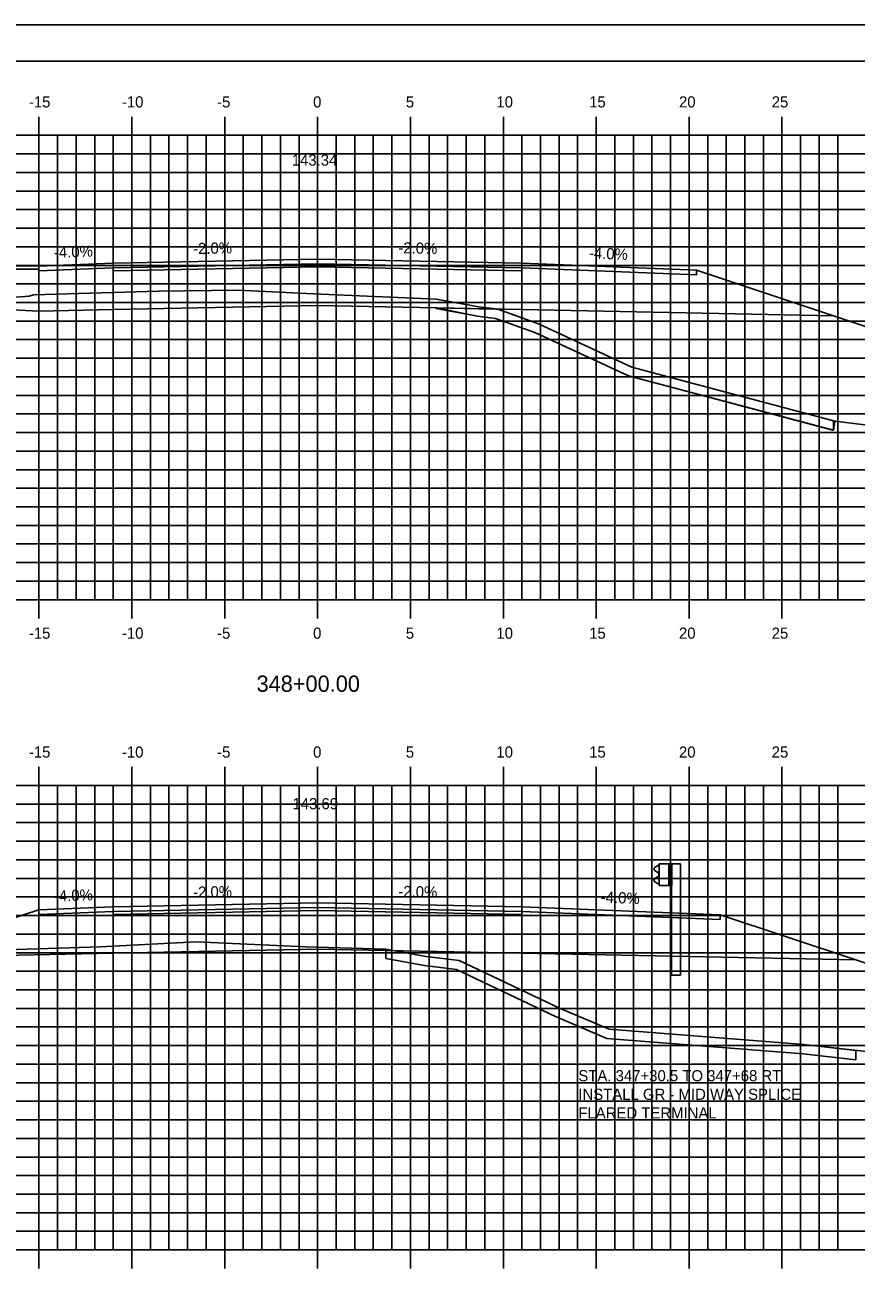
# Model space of a CAD drawing. Extents: x 1144085 to 1144255, y 608981 to 609091.
# Drawn here: x 1144152.6 to 1144197.3, y 609024.1 to 609091.3 of the extents above; entities that cross this region are included whole.
import ezdxf

# ---------------------------------------------------------------- set-up
doc = ezdxf.new("R2010")
doc.units = 0
for name, color, linetype in [('ANNOTATION', 7, 'Continuous'), ('BORDER', 7, 'Continuous'), ('D_Guardrail_Beam_Rt', 7, 'Continuous'), ('D_Guardrail_ConcBarrier', 7, 'Continuous'), ('D_Roadway_Centerline', 7, 'Continuous'), ('D_Roadway_Centerline_Text', 7, 'Continuous'), ('D_Roadway_Edge_Shoulder', 7, 'Continuous'), ('D_Roadway_Edge_TW', 7, 'Continuous'), ('D_Roadway_Pavement', 7, 'Continuous'), ('D_Roadway_SlopeLines', 7, 'Continuous'), ('D_Roadway_SubGrade', 7, 'Continuous'), ('H_V ANNOTATION', 7, 'Continuous'), ('MAJOR', 7, 'Continuous'), ('MINOR', 7, 'Continuous'), ('PLOT BOUNDARY', 7, 'Continuous'), ('S_Roadway_Centerline', 7, 'Continuous'), ('SHADING', 7, 'Continuous')]:
    doc.layers.add(name, color=color, linetype=linetype)

msp = doc.modelspace()

# ---------------------------------------------------------------- linework, layer by layer
for points in [[(1144123.068, 609078.385), (1144153.349, 609078.292), (1144157.349, 609078.452), (1144168.349, 609078.672), (1144179.349, 609078.452), (1144188.751, 609078.076), (1144196.129, 609075.617), (1144199.129, 609074.617), (1144217.63, 609068.45)], [(1144136.907, 609038.164), (1144142.311, 609040.063), (1144145.395, 609041.063), (1144153.348, 609043.642), (1144153.349, 609043.642), (1144157.349, 609043.802), (1144168.349, 609044.022), (1144179.349, 609043.802), (1144190.025, 609043.375), (1144197.322, 609040.943), (1144200.322, 609039.943), (1144215.637, 609034.838)]]:
    msp.add_lwpolyline(points)
at = {"layer": 'BORDER'}
msp.add_lwpolyline([(1144093.349, 608984.335), (1144253.349, 608984.335), (1144253.349, 609089.335), (1144093.349, 609089.335)], close=True, dxfattribs=at)
at = {"layer": 'D_Guardrail_Beam_Rt'}
for p, q in [((1144186.639, 609046.015), (1144186.495, 609045.915)), ((1144186.495, 609045.772), (1144186.691, 609045.636)), ((1144186.729, 609046.036), (1144186.655, 609046.022)), ((1144186.691, 609045.437), (1144186.495, 609045.301)), ((1144186.495, 609045.158), (1144186.639, 609045.058)), ((1144186.655, 609045.051), (1144186.729, 609045.036)), ((1144186.724, 609045.572), (1144186.724, 609045.501))]:
    msp.add_line(p, q, dxfattribs=at)
for centre, major_axis, start_param, end_param in [((1144186.546, 609045.844), (-0.0877, 0), 5.323254, 7.243116), ((1144186.663, 609045.981), (-0.0417, 0), 4.907132, 5.323254), ((1144186.645, 609045.572), (0.0789, 0), 0, 0.959931), ((1144186.546, 609045.229), (-0.0877, 0), 5.323254, 7.243116), ((1144186.663, 609045.092), (-0.0417, 0), 0.959931, 1.376053), ((1144186.645, 609045.501), (0.0789, 0), 5.323254, 6.283185)]:
    msp.add_ellipse(centre, major_axis=major_axis, ratio=0.995501, start_param=start_param, end_param=end_param, dxfattribs=at)
at = {"layer": 'D_Guardrail_ConcBarrier'}
for p, q in [((1144186.729, 609046.12), (1144187.416, 609046.12)), ((1144186.729, 609044.953), (1144186.729, 609046.12)), ((1144187.25, 609046.12), (1144187.25, 609044.953)), ((1144187.354, 609046.12), (1144187.354, 609044.953)), ((1144187.416, 609046.12), (1144187.887, 609046.12)), ((1144187.416, 609046.12), (1144187.416, 609044.953)), ((1144187.887, 609046.12), (1144187.887, 609040.12)), ((1144187.416, 609044.953), (1144186.729, 609044.953)), ((1144187.396, 609040.12), (1144187.396, 609044.953)), ((1144187.396, 609040.12), (1144187.887, 609040.12))]:
    msp.add_line(p, q, dxfattribs=at)
at = {"layer": 'D_Roadway_Edge_Shoulder'}
for points in [[(1144153.349, 609078.292), (1144150.349, 609078.301), (1144150.349, 609078.135), (1144153.349, 609078.126)], [(1144157.349, 609078.452), (1144153.349, 609078.292), (1144153.349, 609078.042), (1144157.349, 609078.202)], [(1144179.349, 609078.452), (1144188.751, 609078.076), (1144188.751, 609077.826), (1144179.349, 609078.202)], [(1144157.349, 609043.802), (1144153.349, 609043.642), (1144153.349, 609043.392), (1144157.349, 609043.552)], [(1144179.349, 609043.802), (1144190.025, 609043.375), (1144190.025, 609043.125), (1144179.349, 609043.552)]]:
    msp.add_lwpolyline(points, close=True, dxfattribs=at)
at = {"layer": 'D_Roadway_Edge_TW'}
for points in [[(1144157.349, 609078.202), (1144157.349, 609078.452), (1144168.349, 609078.672), (1144179.349, 609078.452), (1144179.349, 609078.202), (1144168.349, 609078.422)], [(1144157.349, 609043.552), (1144157.349, 609043.802), (1144168.349, 609044.022), (1144179.349, 609043.802), (1144179.349, 609043.552), (1144168.349, 609043.772)]]:
    msp.add_lwpolyline(points, close=True, dxfattribs=at)
at = {"layer": 'D_Roadway_Pavement'}
for points in [[(1144157.349, 609078.036), (1144157.349, 609078.202), (1144168.349, 609078.422), (1144179.349, 609078.202), (1144179.349, 609078.036), (1144168.349, 609078.256)], [(1144157.349, 609043.386), (1144157.349, 609043.552), (1144168.349, 609043.772), (1144179.349, 609043.552), (1144179.349, 609043.386), (1144168.349, 609043.606)]]:
    msp.add_lwpolyline(points, close=True, dxfattribs=at)
at = {"layer": 'D_Roadway_SlopeLines'}
for p, q in [((1144174.737, 609076.044), (1144174.737, 609076.008)), ((1144196.129, 609069.967), (1144196.129, 609069.455)), ((1144172.025, 609041.53), (1144172.025, 609041.03)), ((1144197.322, 609036.074), (1144197.322, 609035.573))]:
    msp.add_line(p, q, dxfattribs=at)
for points in [[(1144174.737, 609076.008), (1144176.951, 609075.599), (1144177.932, 609075.479), (1144180.051, 609074.727), (1144185.091, 609072.384), (1144196.092, 609069.46), (1144196.129, 609069.455)], [(1144196.129, 609075.617), (1144199.129, 609074.617)], [(1144172.025, 609041.024), (1144174.11, 609040.638), (1144175.834, 609040.428), (1144181.164, 609037.901), (1144183.926, 609036.722), (1144194.481, 609035.887), (1144197.322, 609035.573)], [(1144197.322, 609040.943), (1144200.322, 609039.943)]]:
    msp.add_lwpolyline(points, dxfattribs=at)
at = {"layer": 'D_Roadway_SubGrade'}
for points in [[(1144123.068, 609077.385), (1144153.349, 609075.872), (1144157.349, 609075.952), (1144157.349, 609078.036), (1144157.349, 609078.202), (1144153.349, 609078.042), (1144153.349, 609078.292), (1144123.068, 609078.385)], [(1144157.349, 609075.952), (1144157.349, 609078.036), (1144168.349, 609078.256), (1144179.349, 609078.036), (1144179.349, 609075.952), (1144168.349, 609076.172)], [(1144179.349, 609078.036), (1144179.349, 609078.202), (1144188.751, 609077.826), (1144188.751, 609078.076), (1144188.751, 609078.076), (1144196.129, 609075.617), (1144179.349, 609075.952)], [(1144157.349, 609043.386), (1144157.349, 609043.552), (1144153.349, 609043.392), (1144153.349, 609043.642), (1144153.348, 609043.642), (1144145.395, 609041.063), (1144157.349, 609041.302)], [(1144157.349, 609041.302), (1144157.349, 609043.386), (1144168.349, 609043.606), (1144179.349, 609043.386), (1144179.349, 609041.302), (1144168.349, 609041.522)], [(1144179.349, 609043.386), (1144179.349, 609043.552), (1144190.025, 609043.125), (1144190.025, 609043.375), (1144190.025, 609043.375), (1144197.322, 609040.943), (1144179.349, 609041.302)]]:
    msp.add_lwpolyline(points, close=True, dxfattribs=at)
at = {"layer": 'MAJOR'}
for p, q in [((1144153.349, 609086.337), (1144153.349, 609085.335)), ((1144158.349, 609086.337), (1144158.349, 609085.335)), ((1144163.349, 609086.337), (1144163.349, 609085.335)), ((1144168.349, 609086.337), (1144168.349, 609085.335)), ((1144173.349, 609086.337), (1144173.349, 609085.335)), ((1144178.349, 609086.337), (1144178.349, 609085.335)), ((1144183.349, 609086.337), (1144183.349, 609085.335)), ((1144188.349, 609086.337), (1144188.349, 609085.335)), ((1144193.349, 609086.337), (1144193.349, 609085.335)), ((1144098.349, 609085.335), (1144238.349, 609085.335)), ((1144098.349, 609085.335), (1144238.349, 609085.335)), ((1144153.349, 609060.335), (1144153.349, 609085.335)), ((1144158.349, 609060.335), (1144158.349, 609085.335)), ((1144163.349, 609060.335), (1144163.349, 609085.335)), ((1144168.349, 609060.335), (1144168.349, 609085.335)), ((1144173.349, 609060.335), (1144173.349, 609085.335)), ((1144178.349, 609060.335), (1144178.349, 609085.335)), ((1144183.349, 609060.335), (1144183.349, 609085.335)), ((1144188.349, 609060.335), (1144188.349, 609085.335)), ((1144193.349, 609060.335), (1144193.349, 609085.335)), ((1144098.349, 609080.335), (1144238.349, 609080.335)), ((1144098.349, 609075.335), (1144238.349, 609075.335)), ((1144098.349, 609070.335), (1144238.349, 609070.335)), ((1144098.349, 609065.335), (1144238.349, 609065.335)), ((1144098.349, 609060.335), (1144238.349, 609060.335)), ((1144098.349, 609060.335), (1144238.349, 609060.335)), ((1144153.349, 609059.333), (1144153.349, 609060.335)), ((1144158.349, 609059.333), (1144158.349, 609060.335)), ((1144163.349, 609059.333), (1144163.349, 609060.335)), ((1144168.349, 609059.333), (1144168.349, 609060.335)), ((1144173.349, 609059.333), (1144173.349, 609060.335)), ((1144178.349, 609059.333), (1144178.349, 609060.335)), ((1144183.349, 609059.333), (1144183.349, 609060.335)), ((1144188.349, 609059.333), (1144188.349, 609060.335)), ((1144193.349, 609059.333), (1144193.349, 609060.335)), ((1144153.349, 609051.337), (1144153.349, 609050.335)), ((1144158.349, 609051.337), (1144158.349, 609050.335)), ((1144163.349, 609051.337), (1144163.349, 609050.335)), ((1144168.349, 609051.337), (1144168.349, 609050.335)), ((1144173.349, 609051.337), (1144173.349, 609050.335)), ((1144178.349, 609051.337), (1144178.349, 609050.335)), ((1144183.349, 609051.337), (1144183.349, 609050.335)), ((1144188.349, 609051.337), (1144188.349, 609050.335)), ((1144193.349, 609051.337), (1144193.349, 609050.335)), ((1144098.349, 609050.335), (1144238.349, 609050.335)), ((1144098.349, 609050.335), (1144238.349, 609050.335)), ((1144153.349, 609025.335), (1144153.349, 609050.335)), ((1144158.349, 609025.335), (1144158.349, 609050.335)), ((1144163.349, 609025.335), (1144163.349, 609050.335)), ((1144168.349, 609025.335), (1144168.349, 609050.335)), ((1144173.349, 609025.335), (1144173.349, 609050.335)), ((1144178.349, 609025.335), (1144178.349, 609050.335)), ((1144183.349, 609025.335), (1144183.349, 609050.335)), ((1144188.349, 609025.335), (1144188.349, 609050.335)), ((1144193.349, 609025.335), (1144193.349, 609050.335)), ((1144098.349, 609045.335), (1144238.349, 609045.335)), ((1144098.349, 609040.335), (1144238.349, 609040.335)), ((1144098.349, 609035.335), (1144238.349, 609035.335)), ((1144098.349, 609030.335), (1144238.349, 609030.335)), ((1144098.349, 609025.335), (1144238.349, 609025.335)), ((1144098.349, 609025.335), (1144238.349, 609025.335)), ((1144153.349, 609024.333), (1144153.349, 609025.335)), ((1144158.349, 609024.333), (1144158.349, 609025.335)), ((1144163.349, 609024.333), (1144163.349, 609025.335)), ((1144168.349, 609024.333), (1144168.349, 609025.335)), ((1144173.349, 609024.333), (1144173.349, 609025.335)), ((1144178.349, 609024.333), (1144178.349, 609025.335)), ((1144183.349, 609024.333), (1144183.349, 609025.335)), ((1144188.349, 609024.333), (1144188.349, 609025.335)), ((1144193.349, 609024.333), (1144193.349, 609025.335))]:
    msp.add_line(p, q, dxfattribs=at)
at = {"layer": 'MINOR'}
for p, q in [((1144154.349, 609060.335), (1144154.349, 609085.335)), ((1144155.349, 609060.335), (1144155.349, 609085.335)), ((1144156.349, 609060.335), (1144156.349, 609085.335)), ((1144157.349, 609060.335), (1144157.349, 609085.335)), ((1144159.349, 609060.335), (1144159.349, 609085.335)), ((1144160.349, 609060.335), (1144160.349, 609085.335)), ((1144161.349, 609060.335), (1144161.349, 609085.335)), ((1144162.349, 609060.335), (1144162.349, 609085.335)), ((1144164.349, 609060.335), (1144164.349, 609085.335)), ((1144165.349, 609060.335), (1144165.349, 609085.335)), ((1144166.349, 609060.335), (1144166.349, 609085.335)), ((1144167.349, 609060.335), (1144167.349, 609085.335)), ((1144169.349, 609060.335), (1144169.349, 609085.335)), ((1144170.349, 609060.335), (1144170.349, 609085.335)), ((1144171.349, 609060.335), (1144171.349, 609085.335)), ((1144172.349, 609060.335), (1144172.349, 609085.335)), ((1144174.349, 609060.335), (1144174.349, 609085.335)), ((1144175.349, 609060.335), (1144175.349, 609085.335)), ((1144176.349, 609060.335), (1144176.349, 609085.335)), ((1144177.349, 609060.335), (1144177.349, 609085.335)), ((1144179.349, 609060.335), (1144179.349, 609085.335)), ((1144180.349, 609060.335), (1144180.349, 609085.335)), ((1144181.349, 609060.335), (1144181.349, 609085.335)), ((1144182.349, 609060.335), (1144182.349, 609085.335)), ((1144184.349, 609060.335), (1144184.349, 609085.335)), ((1144185.349, 609060.335), (1144185.349, 609085.335)), ((1144186.349, 609060.335), (1144186.349, 609085.335)), ((1144187.349, 609060.335), (1144187.349, 609085.335)), ((1144189.349, 609060.335), (1144189.349, 609085.335)), ((1144190.349, 609060.335), (1144190.349, 609085.335)), ((1144191.349, 609060.335), (1144191.349, 609085.335)), ((1144192.349, 609060.335), (1144192.349, 609085.335)), ((1144194.349, 609060.335), (1144194.349, 609085.335)), ((1144195.349, 609060.335), (1144195.349, 609085.335)), ((1144196.349, 609060.335), (1144196.349, 609085.335)), ((1144098.349, 609084.335), (1144238.349, 609084.335)), ((1144098.349, 609083.335), (1144238.349, 609083.335)), ((1144098.349, 609082.335), (1144238.349, 609082.335)), ((1144098.349, 609081.335), (1144238.349, 609081.335)), ((1144098.349, 609079.335), (1144238.349, 609079.335)), ((1144098.349, 609078.335), (1144238.349, 609078.335)), ((1144098.349, 609077.335), (1144238.349, 609077.335)), ((1144098.349, 609076.335), (1144238.349, 609076.335)), ((1144098.349, 609074.335), (1144238.349, 609074.335)), ((1144098.349, 609073.335), (1144238.349, 609073.335)), ((1144098.349, 609072.335), (1144238.349, 609072.335)), ((1144098.349, 609071.335), (1144238.349, 609071.335)), ((1144098.349, 609069.335), (1144238.349, 609069.335)), ((1144098.349, 609068.335), (1144238.349, 609068.335)), ((1144098.349, 609067.335), (1144238.349, 609067.335)), ((1144098.349, 609066.335), (1144238.349, 609066.335)), ((1144098.349, 609064.335), (1144238.349, 609064.335)), ((1144098.349, 609063.335), (1144238.349, 609063.335)), ((1144098.349, 609062.335), (1144238.349, 609062.335)), ((1144098.349, 609061.335), (1144238.349, 609061.335)), ((1144154.349, 609025.335), (1144154.349, 609050.335)), ((1144155.349, 609025.335), (1144155.349, 609050.335)), ((1144156.349, 609025.335), (1144156.349, 609050.335)), ((1144157.349, 609025.335), (1144157.349, 609050.335)), ((1144159.349, 609025.335), (1144159.349, 609050.335)), ((1144160.349, 609025.335), (1144160.349, 609050.335)), ((1144161.349, 609025.335), (1144161.349, 609050.335)), ((1144162.349, 609025.335), (1144162.349, 609050.335)), ((1144164.349, 609025.335), (1144164.349, 609050.335)), ((1144165.349, 609025.335), (1144165.349, 609050.335)), ((1144166.349, 609025.335), (1144166.349, 609050.335)), ((1144167.349, 609025.335), (1144167.349, 609050.335)), ((1144169.349, 609025.335), (1144169.349, 609050.335)), ((1144170.349, 609025.335), (1144170.349, 609050.335)), ((1144171.349, 609025.335), (1144171.349, 609050.335)), ((1144172.349, 609025.335), (1144172.349, 609050.335)), ((1144174.349, 609025.335), (1144174.349, 609050.335)), ((1144175.349, 609025.335), (1144175.349, 609050.335)), ((1144176.349, 609025.335), (1144176.349, 609050.335)), ((1144177.349, 609025.335), (1144177.349, 609050.335)), ((1144179.349, 609025.335), (1144179.349, 609050.335)), ((1144180.349, 609025.335), (1144180.349, 609050.335)), ((1144181.349, 609025.335), (1144181.349, 609050.335)), ((1144182.349, 609025.335), (1144182.349, 609050.335)), ((1144184.349, 609025.335), (1144184.349, 609050.335)), ((1144185.349, 609025.335), (1144185.349, 609050.335)), ((1144186.349, 609025.335), (1144186.349, 609050.335)), ((1144187.349, 609025.335), (1144187.349, 609050.335)), ((1144189.349, 609025.335), (1144189.349, 609050.335)), ((1144190.349, 609025.335), (1144190.349, 609050.335)), ((1144191.349, 609025.335), (1144191.349, 609050.335)), ((1144192.349, 609025.335), (1144192.349, 609050.335)), ((1144194.349, 609025.335), (1144194.349, 609050.335)), ((1144195.349, 609025.335), (1144195.349, 609050.335)), ((1144196.349, 609025.335), (1144196.349, 609050.335)), ((1144098.349, 609049.335), (1144238.349, 609049.335)), ((1144098.349, 609048.335), (1144238.349, 609048.335)), ((1144098.349, 609047.335), (1144238.349, 609047.335)), ((1144098.349, 609046.335), (1144238.349, 609046.335)), ((1144098.349, 609044.335), (1144238.349, 609044.335)), ((1144098.349, 609043.335), (1144238.349, 609043.335)), ((1144098.349, 609042.335), (1144238.349, 609042.335)), ((1144098.349, 609041.335), (1144238.349, 609041.335)), ((1144098.349, 609039.335), (1144238.349, 609039.335)), ((1144098.349, 609038.335), (1144238.349, 609038.335)), ((1144098.349, 609037.335), (1144238.349, 609037.335)), ((1144098.349, 609036.335), (1144238.349, 609036.335)), ((1144098.349, 609034.335), (1144238.349, 609034.335)), ((1144098.349, 609033.335), (1144238.349, 609033.335)), ((1144098.349, 609032.335), (1144238.349, 609032.335)), ((1144098.349, 609031.335), (1144238.349, 609031.335)), ((1144098.349, 609029.335), (1144238.349, 609029.335)), ((1144098.349, 609028.335), (1144238.349, 609028.335)), ((1144098.349, 609027.335), (1144238.349, 609027.335)), ((1144098.349, 609026.335), (1144238.349, 609026.335))]:
    msp.add_line(p, q, dxfattribs=at)
at = {"layer": 'PLOT BOUNDARY'}
msp.add_lwpolyline([(1144085.256, 608981.276), (1144255.256, 608981.276), (1144255.256, 609091.276), (1144085.256, 609091.276)], close=True, dxfattribs=at)
at = {"layer": 'S_Roadway_Centerline'}
for points in [[(1144152.016, 609076.628), (1144152.614, 609076.656), (1144152.826, 609076.685), (1144153.049, 609076.743), (1144159.785, 609076.952), (1144164.047, 609076.996), (1144168.131, 609076.81), (1144174.737, 609076.516), (1144177.027, 609076.094), (1144178.047, 609075.968), (1144180.241, 609075.191), (1144185.262, 609072.856), (1144196.187, 609069.952), (1144202.207, 609069.208)], [(1144126.454, 609037.587), (1144128.501, 609037.315), (1144129.255, 609037.532), (1144130.973, 609037.736), (1144131.266, 609037.758), (1144135.518, 609038.06), (1144137.734, 609038.225), (1144143.271, 609039.799), (1144147.322, 609041.116), (1144149.295, 609041.232), (1144150.45, 609041.455), (1144156.669, 609041.645), (1144161.807, 609041.922), (1144167.699, 609041.655), (1144172.025, 609041.53), (1144174.185, 609041.13), (1144175.974, 609040.912), (1144181.368, 609038.355), (1144184.046, 609037.211), (1144194.528, 609036.383), (1144201.114, 609035.654)]]:
    msp.add_lwpolyline(points, dxfattribs=at)
at = {"layer": 'SHADING'}
for p, q in [((1144196.129, 609069.455), (1144196.187, 609069.952)), ((1144172.515, 609041.439), (1144172.025, 609041.449)), ((1144172.025, 609041.449), (1144172.025, 609041.03)), ((1144197.322, 609035.573), (1144197.322, 609036.074))]:
    msp.add_line(p, q, dxfattribs=at)
for points in [[(1144174.737, 609076.044), (1144176.951, 609075.599), (1144177.932, 609075.479), (1144180.051, 609074.727), (1144185.091, 609072.384), (1144196.129, 609069.455)], [(1144177.952, 609075.98), (1144177.025, 609075.999), (1144174.737, 609076.044)], [(1144196.187, 609069.952), (1144185.262, 609072.856), (1144180.241, 609075.191), (1144178.047, 609075.968), (1144177.952, 609075.98)], [(1144172.025, 609041.03), (1144174.11, 609040.638), (1144175.834, 609040.428), (1144181.164, 609037.901), (1144183.926, 609036.722), (1144194.481, 609035.887), (1144197.322, 609035.573)], [(1144197.322, 609036.074), (1144194.528, 609036.383), (1144184.046, 609037.211), (1144181.368, 609038.355), (1144175.974, 609040.912), (1144174.185, 609041.13), (1144172.515, 609041.439)]]:
    msp.add_lwpolyline(points, dxfattribs=at)

# ---------------------------------------------------------------- texts
at = {"layer": 'ANNOTATION'}
for s, rotation, p in [('-4.0%', 2.29061, (1144154.165, 609078.726)), ('-2.0%', 1.14576, (1144161.652, 609078.938)), ('-2.0%', 358.85424, (1144172.692, 609078.986)), ('-4.0%', 357.70939, (1144182.946, 609078.709)), ('-2.0%', 1.14576, (1144161.652, 609044.289)), ('-2.0%', 358.85424, (1144172.692, 609044.336)), ('-4.0%', 2.29061, (1144154.165, 609044.076)), ('-4.0%', 357.70939, (1144183.583, 609044.034))]:
    msp.add_text(s, height=0.6, rotation=rotation, dxfattribs=at).set_placement(p)
for s, p in [('STA. 347+30.5 TO 347+68 RT', (1144182.387, 609034.413)), ('INSTALL GR - MID WAY SPLICE', (1144182.387, 609033.411)), ('FLARED TERMINAL', (1144182.387, 609032.409))]:
    msp.add_text(s, height=0.6, dxfattribs=at).set_placement(p)
at = {"layer": 'D_Roadway_Centerline'}
for s, p in [('C', (1144168.344, 609078.672)), ('L', (1144168.349, 609078.665)), ('C', (1144168.344, 609044.022)), ('L', (1144168.349, 609044.015))]:
    msp.add_text(s, height=0.0146, dxfattribs=at).set_placement(p)
at = {"layer": 'D_Roadway_Centerline_Text'}
for s, p in [('143.34', (1144166.958, 609083.704)), ('143.69', (1144166.996, 609049.054))]:
    msp.add_text(s, height=0.6, dxfattribs=at).set_placement(p)
at = {"layer": 'H_V ANNOTATION'}
for s, height, p in [('-15', 0.6, (1144152.806, 609086.835)), ('-10', 0.6, (1144157.814, 609086.835)), ('-5', 0.6, (1144162.94, 609086.835)), ('0', 0.6, (1144168.108, 609086.835)), ('5', 0.6, (1144173.1, 609086.835)), ('10', 0.6, (1144177.975, 609086.835)), ('15', 0.6, (1144182.967, 609086.835)), ('20', 0.6, (1144187.803, 609086.835)), ('25', 0.6, (1144192.795, 609086.835)), ('-15', 0.6, (1144152.806, 609058.235)), ('-10', 0.6, (1144157.814, 609058.235)), ('-5', 0.6, (1144162.94, 609058.235)), ('0', 0.6, (1144168.108, 609058.235)), ('5', 0.6, (1144173.1, 609058.235)), ('10', 0.6, (1144177.975, 609058.235)), ('15', 0.6, (1144182.967, 609058.235)), ('20', 0.6, (1144187.803, 609058.235)), ('25', 0.6, (1144192.795, 609058.235)), ('348+00.00', 0.875, (1144165.064, 609055.378)), ('-15', 0.6, (1144152.806, 609051.835)), ('-10', 0.6, (1144157.814, 609051.835)), ('-5', 0.6, (1144162.94, 609051.835)), ('0', 0.6, (1144168.108, 609051.835)), ('5', 0.6, (1144173.1, 609051.835)), ('10', 0.6, (1144177.975, 609051.835)), ('15', 0.6, (1144182.967, 609051.835)), ('20', 0.6, (1144187.803, 609051.835)), ('25', 0.6, (1144192.795, 609051.835))]:
    msp.add_text(s, height=height, dxfattribs=at).set_placement(p)
at = {"layer": 'S_Roadway_Centerline'}
for s, p in [('L', (1144164.039, 609076.989)), ('C', (1144164.042, 609076.996)), ('L', (1144161.799, 609041.914)), ('C', (1144161.802, 609041.922))]:
    msp.add_text(s, height=0.0146, dxfattribs=at).set_placement(p)

doc.saveas('drawing.dxf')
